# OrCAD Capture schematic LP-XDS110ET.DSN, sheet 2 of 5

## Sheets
2 2_XDS110: size A3
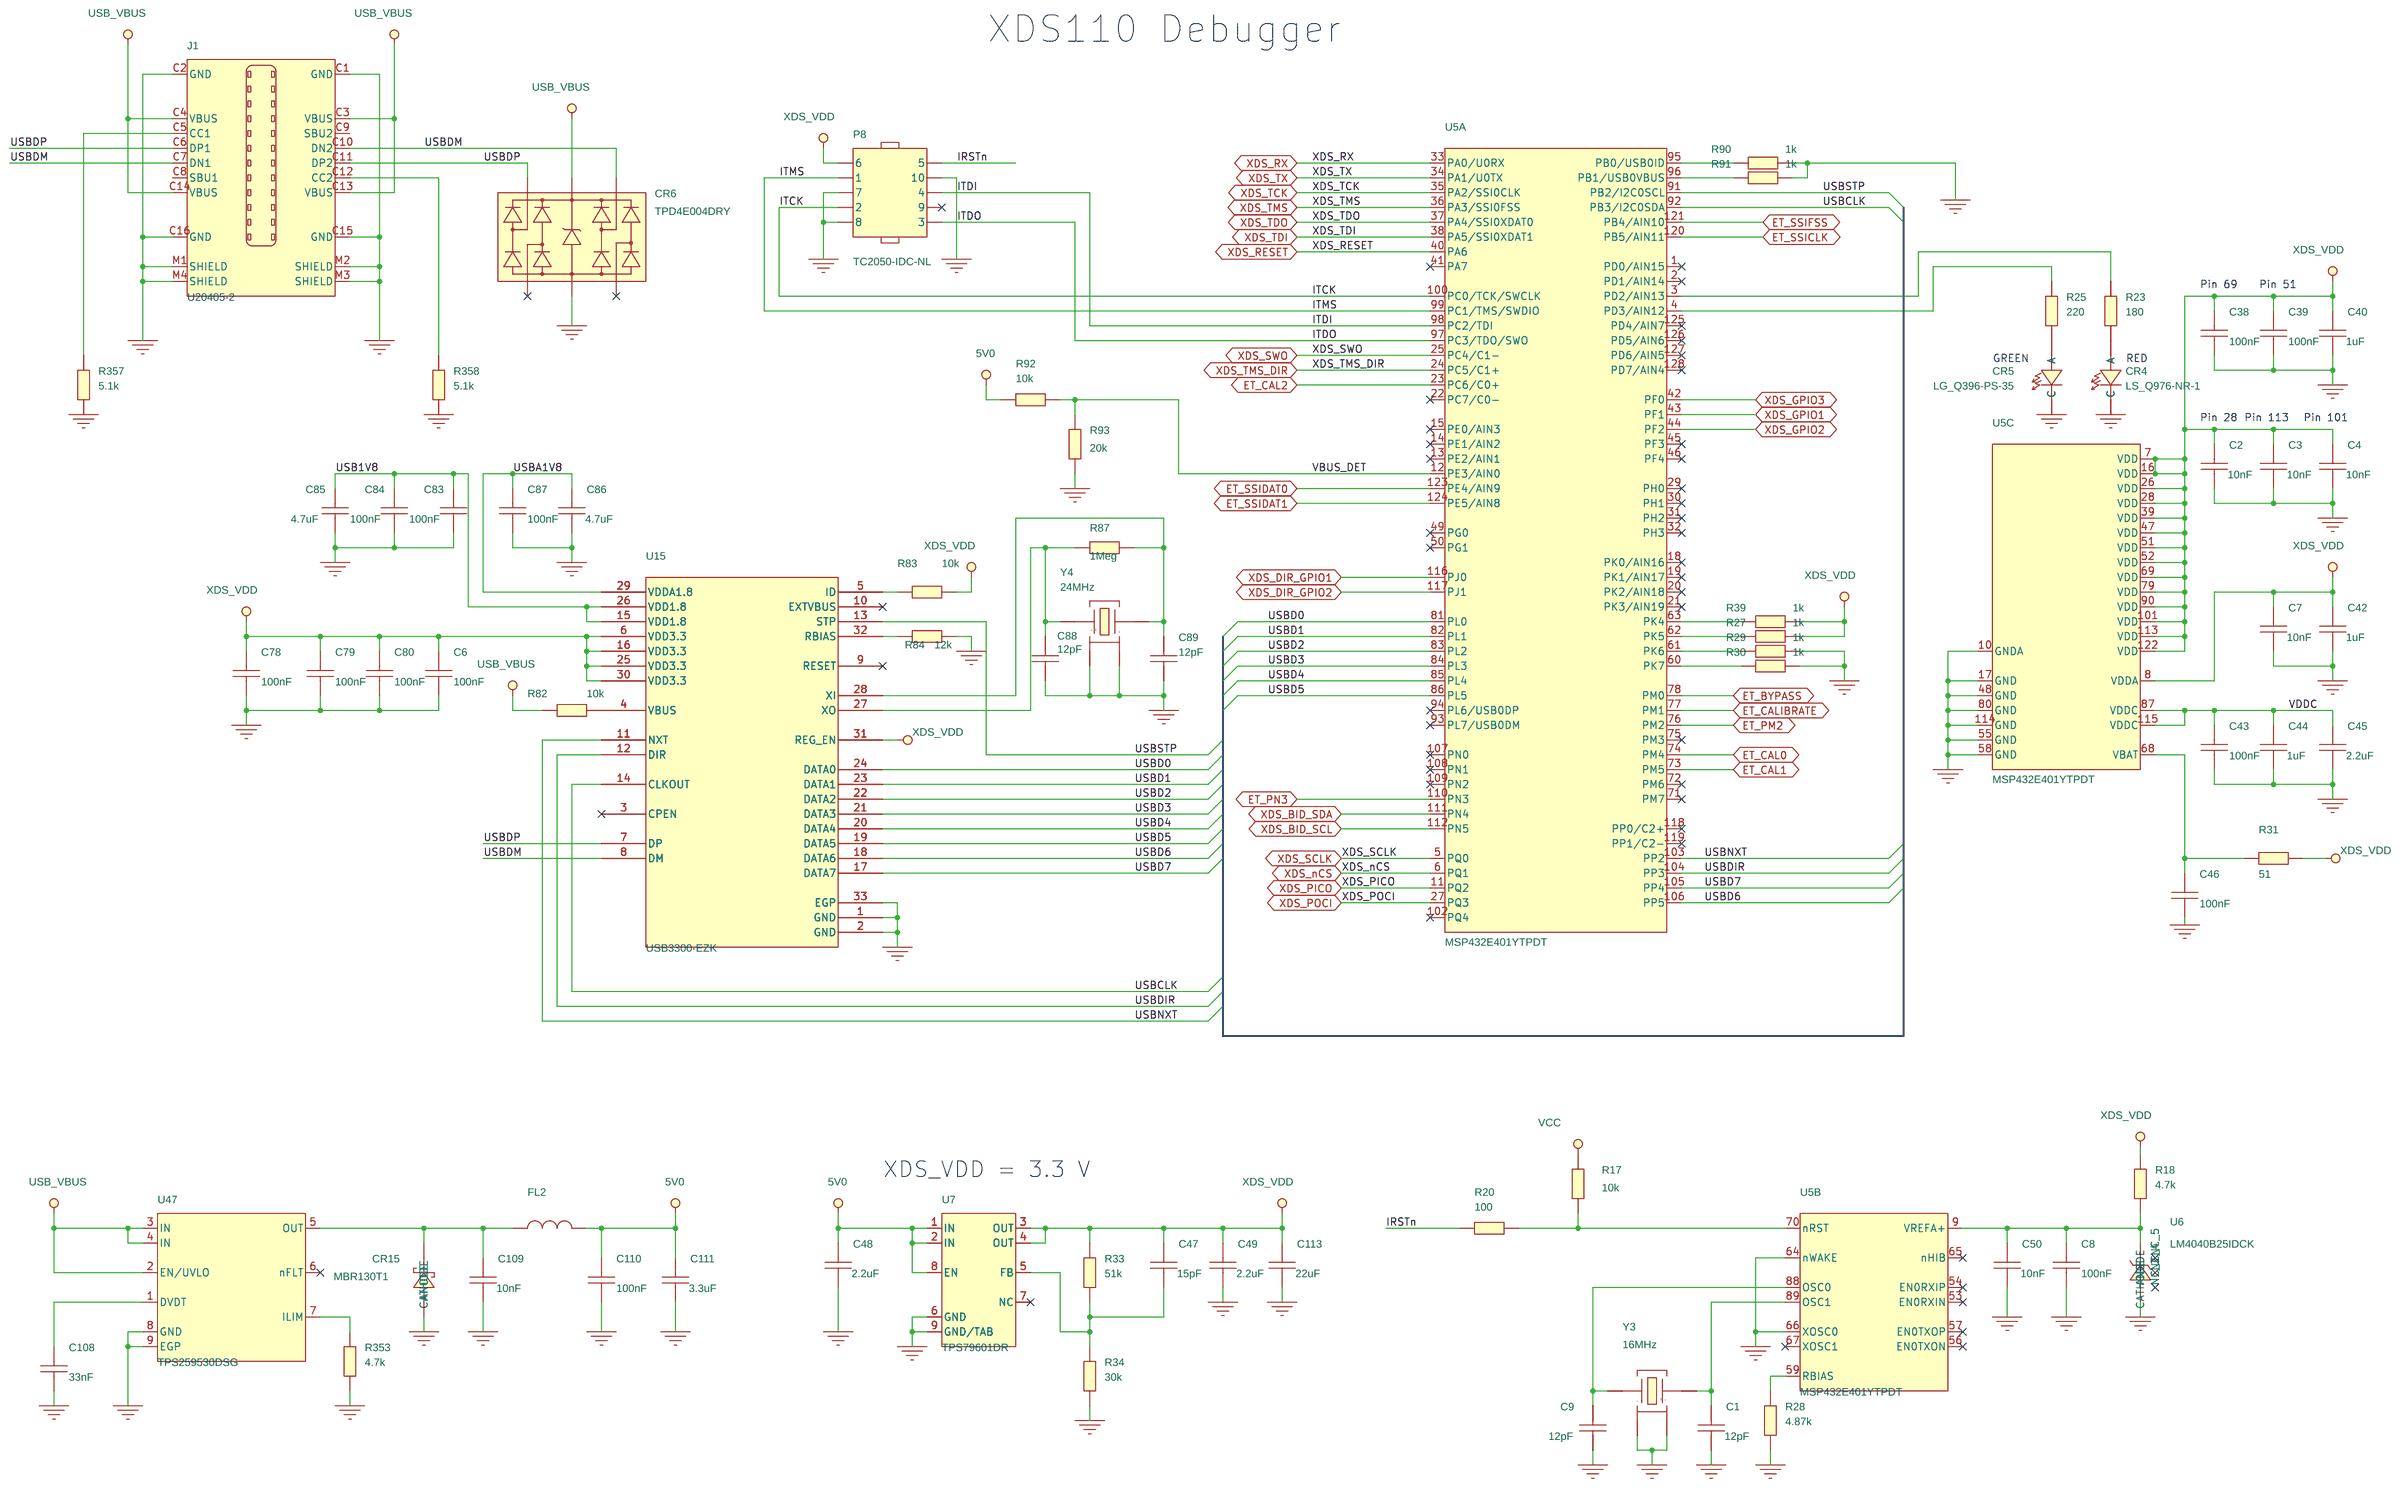
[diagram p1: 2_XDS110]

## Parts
C1  12pF  [CAPC1005X60B2N]
C2  10nF  [CAPC1005X60B2N]
C3  10nF  [CAPC1005X60B2N]
C4  10nF  [CAPC1005X60B2N]
C6  100nF  [CAPC0603X35B2N]
C7  10nF  [CAPC1005X60B2N]
C8  100nF  [CAPC0603X35B2N]
C9  12pF  [CAPC1005X60B2N]
C38  100nF  [CAPC0603X35B2N]
C39  100nF  [CAPC0603X35B2N]
C40  1uF  [CAPC1005X60B2N]
C42  1uF  [CAPC1005X60B2N]
C43  100nF  [CAPC0603X35B2N]
C44  1uF  [CAPC1005X60B2N]
C45  2.2uF  [CAPC1005X60A2N]
C46  100nF  [CAPC0603X35B2N]
C47  15pF  [CAPC1005X60B2N]
C48  2.2uF  [CAPC1005X60A2N]
C49  2.2uF  [CAPC1005X60A2N]
C50  10nF  [CAPC1005X60B2N]
C78  100nF  [CAPC0603X35B2N]
C79  100nF  [CAPC0603X35B2N]
C80  100nF  [CAPC0603X35B2N]
C83  100nF  [CAPC0603X35B2N]
C84  100nF  [CAPC0603X35B2N]
C85  4.7uF  [CAPC1005X60B2N]
C86  4.7uF  [CAPC1005X60B2N]
C87  100nF  [CAPC0603X35B2N]
C88  12pF  [CAPC1005X60B2N]
C89  12pF  [CAPC1005X60B2N]
C108  33nF  [CAPC1005X60A2N]
C109  10nF  [CAPC1005X60B2N]
C110  100nF  [CAPC0603X35B2N]
C111  3.3uF  [CAPC1608X100A2N]
C113  22uF  [CAPC1608X100A2N]
CR4  LS_Q976-NR-1  [LEDC1608X80B2N]
CR5  LG_Q396-PS-35  [LEDC1608X40N]
CR6  TPD4E004DRY  [SON50P100X145X60-6N]
CR15  MBR130T1  [SOD3716X135N]
FL2  BLM18HE152SN1  [FIL_BLM18HE152SN1DN]
J1  U20405-2  [MUP_U204052_A2N]
P8  TC2050-IDC-NL  [TAGCONNECT_TC2050IDCNL_A2N]
R17  10k  [RESC0603X35B2N]
R18  4.7k  [RESC1005X40B2N]
R20  100  [RESC1005X40B2N]
R23  180  [RESC1005X40B2N]
R25  220  [RESC1005X40B2N]
R27  1k  [RESC0603X35B2N]
R28  4.87k  [RESC1005X40B2N]
R29  1k  [RESC0603X35B2N]
R30  1k  [RESC0603X35B2N]
R31  51  [RESC0603X35B2N]
R33  51k  [RESC1005X40B2N]
R34  30k  [RESC1005X40B2N]
R39  1k  [RESC0603X35B2N]
R82  10k  [RESC0603X35B2N]
R83  10k  [RESC0603X35B2N]
R84  12k  [RESC0603X35B2N]
R87  1Meg  [RESC1005X40B2N]
R90  1k  [RESC0603X35B2N]
R91  1k  [RESC0603X35B2N]
R92  10k  [RESC0603X35B2N]
R93  20k  [RESC0603X35B2N]
R353  4.7k  [RESC1005X40B2N]
R357  5.1k  [RESC0603X35B2N]
R358  5.1k  [RESC0603X35B2N]
U5  MSP432E401YTPDT  [QFP40P1600X1600X120-128A2N]  (sections A,B,C)
U6  LM4040B25IDCK  [SOT65P210X110-5N]
U7  TPS79601DR  [SON65P300X300X100-9AN]
U15  USB3300-EZK  [QFNWB50P500X500X100-33N]
U47  TPS259530DSG  [SON50P200X200X80-9A2N]
Y3  16MHz  [OSCCC250X320X100-4BN]
Y4  24MHz  [OSCCC250X320X70-4AN]

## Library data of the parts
C1 C9 C88 C89 = CAPACITOR: CAPACITOR, CERAMIC C0G/NP0, 12pF, 50V, -5%/+5%, -55DEGC/+125DEGC, 0402, SMD; Additional Datasheet URL: http://psearch.en.murata.com/capacitor/product/GRM1555C1H120JA01%23.html; AutoDoc File: https://notefied-dynamic-precision.com/DB/Apps/Desktop/Item/Object.aspx?id=113345; BU Name: TEXAS INSTRUMENTS NORWAY; Budget Currency: EUR; Budget Price: 0.007; Budgetary Price: 0.007 EUR; Country of Origin: Philippines; Datasheet URL: http://psearch.murata.com/capacitor/product/GRM1555C1H120JA01%23.pdf; Datasheet URL 1: http://psearch.murata.com/capacitor/product/GRM1555C1H120JA01%23.pdf; Datasheet URL 2: http://search.murata.co.jp/Ceramy/image/img/w_hinm/L0005E.pdf; Definied Quality: INDUSTRIAL; Dielectric Type: C0G/NP0; Esd Level: N/A; Exclusive for Customers: TEXAS INSTRUMENTS NORWAY; Lead Time: 12; LifeCycle Status: ACTIVE; MPN: CAPACITOR_0402_12pF_C0G/NP0_M_+/-5%_50V; MPN Status: ACTIVE; MSL: N/A; MTBF: N/A; MTBF Standard: N/A; Manufacturer: MANUFACTURER SELECTION; Mass: 0.0016g; Max Oper Temp: +125DEGC; Max Tol: +5%; Maximum Operating Temperature: +125DEGC; Maximum Tolerance: +5%; Min Oper Temp: -55DEGC; Min Tol: -5%; Minimum Operating Temperature: -55DEGC; Minimum Tolerance: -5%; Mounting Type: SMD; NOTE Status: PREFERRED; NOTEfied URL: https://notefied-dynamic-precision.com/NOTEfiedWebInterface/part/show?partNumber=02-07617; Notes: Standard item: Duplicate Reason: custom footprint for TEXAS INSTRUMENTS NORWAY.; Old Footprint: CAPC1005X60N; PCB Package: 0402; Packing Size: 10000; Packing Type: Tape & Reel; Part Number: 02-07617; Part Type: Capacitor|CERAMIC|0402|STANDARD; REACH/SVHC Compliance: Compliant; REACH/SVHC Details: SVHC List Version Jul 7, 2017; REACH/SVHC Source: REACH Declaration; REACH/SVHC Status: Unaffected; REACH/SVHC_COMPLIANCE: COMPLIANT; REACH/SVHC_DETAILS: SVHC LIST VERSION Dec 17, 2015; REACH/SVHC_SOURCE: REACH DECLARATION; REACH/SVHC_STATUS: UNAFFECTED; ROHS: Compliant; Rated Voltage: 50V; Revision: R009; RoHS Status: ROHS_COMPLIANT; Rtd Voltage: 50V; Status: Released; Texas Part Status: Under Review; Type: Capacitor; Vendor: MURATA; Vendor Part Number: GRM1555C1H120JA01D; Vendor Part Status: Active; WEIGHT: 0.0016g
C2-C4 C7 C50 = CAPACITOR: CAPACITOR, CERAMIC X7R, 10nF, 25V, -10%/+10%, -55DEGC/+125DEGC, 0402, SMD; Additional Datasheet URL: http://psearch.en.murata.com/capacitor/product/GRM155R71E103KA01%23.html; AutoDoc File: https://notefied-dynamic-precision.com/DB/Apps/Desktop/Item/Object.aspx?id=114570; BU Name: TEXAS INSTRUMENTS NORWAY; Budget Currency: EUR; Budget Price: 0.003; Budgetary Price: 0.003 EUR; Client Status: UNDER_REVIEW; Country of Origin: China; Datasheet URL: http://psearch.murata.com/capacitor/product/GRM155R71E103KA01%23.pdf; Datasheet URL 1: http://psearch.murata.com/capacitor/product/GRM155R71E103KA01%23.pdf; Datasheet URL 2: http://search.murata.co.jp/Ceramy/image/img/w_hinm/L0005E.pdf; Definied Quality: INDUSTRIAL; Dielectric Type: X7R; Esd Level: N/A; Exclusive for Customers: TEXAS INSTRUMENTS NORWAY; Lead Time: 18; LifeCycle Status: ACTIVE; MPN: CAPACITOR_0402_10nF_X7R_M_+/-10%_25V; MPN Status: ACTIVE; MSL: N/A; MTBF: N/A; MTBF Standard: N/A; Manufacturer: MANUFACTURER SELECTION; Mass: 0.0016g; Max Oper Temp: +125DEGC; Max Tol: +10%; Maximum Operating Temperature: +125DEGC; Maximum Tolerance: +10%; Min Oper Temp: -55DEGC; Min Tol: -10%; Minimum Operating Temperature: -55DEGC; Minimum Tolerance: -10%; Mounting Type: SMD; NOTE Status: PREFERRED; NOTEfied URL: https://notefied-dynamic-precision.com/NOTEfiedWebInterface/part/show?partNumber=02-07775; Notes: Standard item: Duplicate Reason: custom footprint for TEXAS INSTRUMENTS NORWAY.; Old Footprint: CAPC1005X60N; PCB Package: 0402; Packing Size: 10000; Packing Type: Tape & Reel; Part Number: 02-07775; Part Type: Capacitor|CERAMIC|0402|STANDARD; REACH/SVHC Compliance: Compliant; REACH/SVHC Details: SVHC List Version Jul 7, 2017; REACH/SVHC Source: REACH Declaration; REACH/SVHC Status: Unaffected; REACH/SVHC_COMPLIANCE: COMPLIANT; REACH/SVHC_DETAILS: SVHC LIST VERSION Dec 17, 2015; REACH/SVHC_SOURCE: MATERIAL DECLARATION; REACH/SVHC_STATUS: UNAFFECTED; ROHS: Compliant; Rated Voltage: 25V; Revision: R013; RoHS Status: ROHS_COMPLIANT; Rtd Voltage: 25V; Status: Released; Texas Part Status: Under Review; Type: Capacitor; Vendor: MURATA; Vendor Part Number: GRM155R71E103KA01D; Vendor Part Status: Active; WEIGHT: 0.0016g
C6 C8 C38 C39 C43 C46 C78-C80 C110 = CAPACITOR: CAPACITOR, CERAMIC X5R, 100nF, 10V, -10%/+10%, -55DEGC/+85DEGC, 0201, SMD; ALT_SYMBOLS: CAPC0603X35B2L,CAPC0603X35B2M; Additional Datasheet URL: http://psearch.en.murata.com/capacitor/product/GRM033R61A104KE84%23.html; AutoDoc File: https://notefied-dynamic-precision.com/DB/Apps/Desktop/Item/Object.aspx?id=96679; BU Name: DYNAMIC PRECISION GDANSK; Budget Currency: EUR; Budget Price: 0.008; Budgetary Price: 0.008 EUR; Client Status: UNDER_REVIEW; Country of Origin: Missing Info; Datasheet URL: http://psearch.murata.com/capacitor/product/GRM033R61A104KE84%23.pdf; Datasheet URL 1: http://psearch.murata.com/capacitor/product/GRM033R61A104KE84%23.pdf; Datasheet URL 2: http://search.murata.co.jp/Ceramy/image/img/w_hinm/L0005E.pdf; Dielectric Type: X5R; Lead Time: 17; LifeCycle Status: ACTIVE; MPN: GRM155R70J104KA01D; MPN Status: ACTIVE; Manufacturer: MURATA; Mass: 0.00033g; Max Oper Temp: +85DEGC; Max Tol: +10%; Maximum Operating Temperature: +85DEGC; Maximum Tolerance: +10%; Min Oper Temp: -55DEGC; Min Tol: -10%; Minimum Operating Temperature: -55DEGC; Minimum Tolerance: -10%; Mounting Type: SMD; NOTE Status: PREFERRED; NOTEfied URL: https://notefied-dynamic-precision.com/NOTEfiedWebInterface/part/show?partNumber=02-06085; Old Footprint: CAPC1005X60N,0402; PCB Package: 0201; Packing Size: 15000; Packing Type: Tape & Reel; Part Number: 02-06085; Part Type: Capacitor|CERAMIC|0201|STANDARD; REACH/SVHC Compliance: Compliant; REACH/SVHC Details: SVHC List Version Jul 7, 2017; REACH/SVHC Source: REACH Declaration; REACH/SVHC Status: Unaffected; REACH/SVHC_COMPLIANCE: COMPLIANT; REACH/SVHC_DETAILS: SVHC LIST VERSION Jun 20, 2016; REACH/SVHC_SOURCE: REACH DECLARATION; REACH/SVHC_STATUS: UNAFFECTED; ROHS: Compliant; Rated Voltage: 10V; Revision: R011; RoHS Status: ROHS_COMPLIANT; Rtd Voltage: 10V; Status: Released; Texas Part Status: Under Review; Type: Capacitor; Vendor: MURATA; Vendor Part Number: GRM033R61A104KE84D; Vendor Part Status: Active; WEIGHT: 0.00033g
C40 C42 C44 = CAPACITOR: CAPACITOR, CERAMIC X5R, 1uF, 16V, -10%/+10%, -55DEGC/+85DEGC, 0402, SMD; Additional Datasheet URL: http://psearch.en.murata.com/capacitor/product/GRM155R61C105KA12%23.html; AutoDoc File: https://notefied-dynamic-precision.com/DB/Apps/Desktop/Item/Object.aspx?id=115295; BU Name: TEXAS INSTRUMENTS NORWAY; Client Status: UNDER_REVIEW; Datasheet URL: http://psearch.murata.com/capacitor/product/GRM155R61C105KA12%23.pdf; Datasheet URL 1: http://psearch.en.murata.com/capacitor/product/GRM155R61C105KA12%23.pdf; Datasheet URL 2: http://search.murata.co.jp/Ceramy/image/img/w_hinm/L0005E.pdf; Definied Quality: INDUSTRIAL; Dielectric Type: X5R; Esd Level: N/A; MPN: GRM155R61A105KE15D; MPN Status: ACTIVE; MSL: 1; MTBF: N/A; MTBF Standard: N/A; Manufacturer: MURATA; Mass: 0.0016g; Max Oper Temp: +85DEGC; Max Tol: +10%; Maximum Operating Temperature: +85DEGC; Maximum Tolerance: +10%; Min Oper Temp: -55DEGC; Min Tol: -10%; Minimum Operating Temperature: -55DEGC; Minimum Tolerance: -10%; Mounting Type: SMD; NOTE Status: PREFERRED; NOTEfied URL: https://notefied-dynamic-precision.com/NOTEfiedWebInterface/part/show?partNumber=02-07863; Old Footprint: CAPC1005X60N,0402; PCB Package: 0402; Packing Size: 10000; Packing Type: Tape & Reel; Part Number: 02-07863; Part Type: Capacitor|CERAMIC|0402|STANDARD; REACH/SVHC Compliance: Compliant; REACH/SVHC Details: SVHC List Version Jul 7, 2017; REACH/SVHC Source: REACH Declaration; REACH/SVHC Status: Unaffected; REACH/SVHC_COMPLIANCE: COMPLIANT; REACH/SVHC_DETAILS: SVHC LIST VERSION Jun 20, 2016; REACH/SVHC_SOURCE: REACH DECLARATION; REACH/SVHC_STATUS: UNAFFECTED; ROHS: Compliant; Rated Voltage: 16V; Revision: R008; RoHS Status: ROHS_COMPLIANT; Rtd Voltage: 16V; Status: Released; Texas Part Status: Under Review; Type: Capacitor; Vendor: MURATA; Vendor Part Number: GRM155R61C105KA12D; Vendor Part Status: Active; WEIGHT: 0.0016g
C45 C48 C49 = CAPACITOR: CAPACITOR, CERAMIC X5R, 2.2uF, 25V, -10%/+10%, -55DEGC/+85DEGC, 0402, SMD; ALT_SYMBOLS: CAPC1005X60A2L,CAPC1005X60A2M; Additional Datasheet URL: http://search.murata.co.jp/Ceramy/image/img/w_hinm/L0005E.pdf; AutoDoc File: https://notefied-dynamic-precision.com/DB/Apps/Desktop/Item/Object.aspx?id=96297; BU Name: DYNAMIC PRECISION GDANSK; Budget Currency: EUR; Budget Price: 0.063; Budgetary Price: 0.063 EUR; Client Status: UNDER_REVIEW; Country of Origin: Missing Info; Datasheet URL: http://psearch.murata.com/capacitor/product/GRM155R61E225KE11%23.pdf; Datasheet URL 1: http://psearch.murata.com/capacitor/product/GRM155R61E225KE11%23.pdf; Datasheet URL 2: http://search.murata.co.jp/Ceramy/image/img/w_hinm/L0005E.pdf; Definied Quality: INDUSTRIAL; Dielectric Type: X5R; Esd Level: N/A; Lead Time: 19; LifeCycle Status: NRND; MPN: GRM155R60J225KE95D; MPN Status: NRND; MSL: 1; MTBF: N/A; MTBF Standard: N/A; Manufacturer: MURATA; Mass: 0.0031g; Max Oper Temp: +85DEGC; Max Tol: +10%; Maximum Operating Temperature: +85DEGC; Maximum Tolerance: +10%; Min Oper Temp: -55DEGC; Min Tol: -10%; Minimum Operating Temperature: -55DEGC; Minimum Tolerance: -10%; Mounting Type: SMD; NOTE Status: PREFERRED; NOTEfied URL: https://notefied-dynamic-precision.com/NOTEfiedWebInterface/part/show?partNumber=02-06058; Old Footprint: CAPC1005X60N; PCB Package: 0402; Packing Size: 10000; Packing Type: Tape & Reel; Part Number: 02-06058; Part Type: Capacitor|CERAMIC|0402|STANDARD; REACH/SVHC Compliance: Compliant; REACH/SVHC Details: SVHC List Version Jul 7, 2017; REACH/SVHC Source: REACH Declaration; REACH/SVHC Status: Unaffected; REACH/SVHC_COMPLIANCE: COMPLIANT; REACH/SVHC_DETAILS: SVHC List Version Jun 20, 2016; REACH/SVHC_SOURCE: REACH DECLARATION; REACH/SVHC_STATUS: UNAFFECTED; ROHS: Compliant; Rated Voltage: 25V; Revision: R007; RoHS Status: ROHS_COMPLIANT; Rtd Voltage: 25V; Status: Released; Texas Part Status: Under Review; Type: Capacitor; Vendor: MURATA; Vendor Part Number: GRM155R61E225KE11D; Vendor Part Status: Active; WEIGHT: 0.0031g
C47 = CAPACITOR: CAPACITOR, CERAMIC C0G/NP0, 15pF, 50V, -5%/+5%, -55DEGC/+125DEGC, 0402, SMD; Additional Datasheet URL: http://psearch.en.murata.com/capacitor/product/GRM1555C1H150JA01%23.html; AutoDoc File: https://notefied-dynamic-precision.com/DB/Apps/Desktop/Item/Object.aspx?id=114571; BU Name: TEXAS INSTRUMENTS NORWAY; Budget Currency: EUR; Budget Price: 0.006; Budgetary Price: 0.006 EUR; Client Status: UNDER_REVIEW; Country of Origin: Philippines; Datasheet URL: http://psearch.murata.com/capacitor/product/GRM1555C1H150JA01%23.pdf; Datasheet URL 1: http://psearch.murata.com/capacitor/product/GRM1555C1H150JA01%23.pdf; Datasheet URL 2: http://search.murata.co.jp/Ceramy/image/img/w_hinm/L0005E.pdf; Definied Quality: INDUSTRIAL; Dielectric Type: C0G/NP0; Esd Level: N/A; Exclusive for Customers: TEXAS INSTRUMENTS NORWAY; Lead Time: 12; LifeCycle Status: ACTIVE; MPN: CAPACITOR_0402_15pF_C0G/NP0_M_+/-5%_50V; MPN Status: ACTIVE; MSL: N/A; MTBF: N/A; MTBF Standard: N/A; Manufacturer: MANUFACTURER SELECTION; Mass: 0.0016g; Max Oper Temp: +125DEGC; Max Tol: +5%; Maximum Operating Temperature: +125DEGC; Maximum Tolerance: +5%; Min Oper Temp: -55DEGC; Min Tol: -5%; Minimum Operating Temperature: -55DEGC; Minimum Tolerance: -5%; Mounting Type: SMD; NOTE Status: PREFERRED; NOTEfied URL: https://notefied-dynamic-precision.com/NOTEfiedWebInterface/part/show?partNumber=02-07776; Notes: Standard item: Duplicate Reason: custom footprint for TEXAS INSTRUMENTS NORWAY.; Old Footprint: CAPC1005X60N; PCB Package: 0402; Packing Size: 10000; Packing Type: Tape & Reel; Part Number: 02-07776; Part Type: Capacitor|CERAMIC|0402|STANDARD; REACH/SVHC Compliance: Compliant; REACH/SVHC Details: SVHC List Version Jul 7, 2017; REACH/SVHC Source: REACH Declaration; REACH/SVHC Status: Unaffected; REACH/SVHC_COMPLIANCE: COMPLIANT; REACH/SVHC_DETAILS: SVHC LIST VERSION Dec 17, 2015; REACH/SVHC_SOURCE: REACH DECLARATION; REACH/SVHC_STATUS: UNAFFECTED; ROHS: Compliant; Rated Voltage: 50V; Revision: R009; RoHS Status: ROHS_COMPLIANT; Rtd Voltage: 50V; Status: Released; Texas Part Status: Under Review; Type: Capacitor; Vendor: MURATA; Vendor Part Number: GRM1555C1H150JA01D; Vendor Part Status: Active; WEIGHT: 0.0016g
C83 C84 C87 = CAPACITOR: CAPACITOR, CERAMIC X5R, 100nF, 10V, -10%/+10%, -55DEGC/+85DEGC, 0201, SMD; ALT_SYMBOLS: CAPC0603X35B2L,CAPC0603X35B2M; Additional Datasheet URL: http://psearch.en.murata.com/capacitor/product/GRM033R61A104KE84%23.html; AutoDoc File: https://notefied-dynamic-precision.com/DB/Apps/Desktop/Item/Object.aspx?id=96679; BU Name: DYNAMIC PRECISION GDANSK; Budget Currency: EUR; Budget Price: 0.008; Budgetary Price: 0.008 EUR; Client Status: UNDER_REVIEW; Country of Origin: Missing Info; Datasheet URL: http://psearch.murata.com/capacitor/product/GRM033R61A104KE84%23.pdf; Datasheet URL 1: http://psearch.murata.com/capacitor/product/GRM033R61A104KE84%23.pdf; Datasheet URL 2: N/A; Dielectric Type: X5R; Lead Time: 17; LifeCycle Status: ACTIVE; MPN: GRM155R70J104KA01D; MPN Status: ACTIVE; Manufacturer: MURATA; Mass: 0.00033g; Max Oper Temp: +85DEGC; Max Tol: +10%; Maximum Operating Temperature: +85DEGC; Maximum Tolerance: +10%; Min Oper Temp: -55DEGC; Min Tol: -10%; Minimum Operating Temperature: -55DEGC; Minimum Tolerance: -10%; Mounting Type: SMD; NOTE Status: PREFERRED; NOTEfied URL: https://notefied-dynamic-precision.com/NOTEfiedWebInterface/part/show?partNumber=02-06085; Old Footprint: CAPC1005X60N,0402; PCB Package: 0201; Packing Size: 15000; Packing Type: Tape & Reel; Part Number: 02-06085; Part Type: Capacitor|CERAMIC|0201|STANDARD; REACH/SVHC Compliance: Compliant; REACH/SVHC Details: SVHC List Version Jul 7, 2017; REACH/SVHC Source: REACH Declaration; REACH/SVHC Status: Unaffected; REACH/SVHC_COMPLIANCE: COMPLIANT; REACH/SVHC_DETAILS: SVHC LIST VERSION Dec 17, 2015; REACH/SVHC_SOURCE: REACH DECLARATION; REACH/SVHC_STATUS: UNAFFECTED; ROHS: Compliant; Rated Voltage: 10V; Revision: R011; RoHS Status: ROHS_COMPLIANT; Rtd Voltage: 10V; Status: Released; Texas Part Status: Under Review; Type: Capacitor; Vendor: MURATA; Vendor Part Number: GRM033R61A104KE84D; Vendor Part Status: Active; WEIGHT: 0.00033g
C85 C86 = CAPACITOR: CAPACITOR, CERAMIC X5R, 4.7uF, 6.3V, -20%/+20%, -55DEGC/+85DEGC, 0402, SMD; Additional Datasheet URL: https://search.murata.co.jp/Ceramy/image/img/A01X/G101/ENG/GRM155R60J475ME87-01A.pdf; Budgetary Price: 0.0198 USD; Country of Origin: Philippines; Datasheet URL: https://www.murata.com/-/media/webrenewal/support/library/catalog/products/capacitor/mlcc/c02e.ashx?la=en-gb; Dielectric Type: X5R; Exclusive for Customers: TEXAS INSTRUMENTS NORWAY; Lead Time: 11; Mass: 0.0025g; Maximum Operating Temperature: +85DEGC; Maximum Tolerance: +20%; Minimum Operating Temperature: -55DEGC; Minimum Tolerance: -20%; Mounting Type: SMD; NOTEfied URL: https://notefied-dynamic-precision.com/NOTEfiedWebInterface/part/show?partNumber=02-07629; Notes: Standard item: Duplicate Reason: custom footprint for TEXAS INSTRUMENTS NORWAY.; PCB Package: 0402; Packing Size: 10000; Packing Type: Tape & Reel; Part Number: 02-07629; Part Type: Capacitor|CERAMIC|0402|STANDARD; REACH/SVHC Compliance: Compliant; REACH/SVHC Details: SVHC List Version Jul 7, 2017; REACH/SVHC Source: REACH Declaration; REACH/SVHC Status: Unaffected; ROHS: Compliant; Rated Voltage: 6.3V; Revision: R027; Status: Released; Texas Part Status: Under Review; Type: Capacitor; Vendor: MURATA; Vendor Part Number: GRM155R60J475ME87D; Vendor Part Status: Active
C108 = CAPACITOR: CAPACITOR, CERAMIC X7R, 33nF, 25V, -10%/+10%, -55DEGC/+125DEGC, 0402, SMD; ALT_SYMBOLS: CAPC1005X60A2L,CAPC1005X60A2M; Additional Datasheet URL: http://psearch.en.murata.com/capacitor/product/GRM155R71E333KA88%23.html; AutoDoc File: https://notefied-dynamic-precision.com/DB/Apps/Desktop/Item/Object.aspx?id=115293; BU Name: TEXAS INSTRUMENTS NORWAY; Budgetary Price: 0.013 EUR; Client Status: UNDER_REVIEW; Country of Origin: Philippines,China; Datasheet URL: https://search.murata.co.jp/Ceramy/image/img/A01X/G101/ENG/GRM155R71E333KA88-01A.pdf; Datasheet URL 1: http://psearch.en.murata.com/capacitor/product/GRM155R71E104KE14%23.pdf; Datasheet URL 2: http://search.murata.co.jp/Ceramy/image/img/w_hinm/L0005E.pdf; Dielectric Type: X7R; Lead Time: 12; LifeCycle Status: ACTIVE; MPN: GRM155R70J104KA01D; MPN Status: ACTIVE; Manufacturer: MURATA; Mass: 0.0016g; Max Oper Temp: +125DEGC; Max Tol: +10%; Maximum Operating Temperature: +125DEGC; Maximum Tolerance: +10%; Min Oper Temp: -55DEGC; Min Tol: -10%; Minimum Operating Temperature: -55DEGC; Minimum Tolerance: -10%; Mounting Type: SMD; NOTE Status: PREFERRED; NOTEfied URL: https://notefied-dynamic-precision.com/NOTEfiedWebInterface/part/show?partNumber=02-04479; Old Footprint: CAPC1005X60N,0402; PCB Package: 0402; Packing Size: 10000; Packing Type: Tape & Reel; Part Number: 02-04479; Part Type: Capacitor|CERAMIC|0402|STANDARD; REACH/SVHC_COMPLIANCE: COMPLIANT; REACH/SVHC_DETAILS: SVHC LIST VERSION Jun 20, 2016; REACH/SVHC_SOURCE: REACH DECLARATION; REACH/SVHC_STATUS: UNAFFECTED; ROHS: Compliant; Rated Voltage: 25V; Revision: R017; RoHS Status: ROHS_COMPLIANT; Rtd Voltage: 25V; Status: Released; Type: Capacitor; Vendor: MURATA; Vendor Part Number: GRM155R71E333KA88D; Vendor Part Status: Active; WEIGHT: 0.0016g
C109 = CAPACITOR: CAPACITOR, CERAMIC X7R, 10nF, 25V, -10%/+10%, -55DEGC/+125DEGC, 0402, SMD; Additional Datasheet URL: http://psearch.en.murata.com/capacitor/product/GRM155R71E103KA01%23.html; Budgetary Price: 0.003 EUR; Country of Origin: China; Datasheet URL: https://search.murata.co.jp/Ceramy/image/img/A01X/G101/ENG/GRM155R71E103KA01-01A.pdf; Dielectric Type: X7R; Exclusive for Customers: TEXAS INSTRUMENTS NORWAY; Lead Time: 18; Mass: 0.0016g; Maximum Operating Temperature: +125DEGC; Maximum Tolerance: +10%; Minimum Operating Temperature: -55DEGC; Minimum Tolerance: -10%; Mounting Type: SMD; NOTEfied URL: https://notefied-dynamic-precision.com/NOTEfiedWebInterface/part/show?partNumber=02-07775; Notes: Standard item: Duplicate Reason: custom footprint for TEXAS INSTRUMENTS NORWAY.; PCB Package: 0402; Packing Size: 10000; Packing Type: Tape & Reel; Part Number: 02-07775; Part Type: Capacitor|CERAMIC|0402|STANDARD; REACH/SVHC Compliance: Compliant; REACH/SVHC Details: SVHC List Version Jul 7, 2017; REACH/SVHC Source: REACH Declaration; REACH/SVHC Status: Unaffected; ROHS: Compliant; Rated Voltage: 25V; Revision: R015; Status: Released; Texas Part Status: Under Review; Type: Capacitor; Vendor: MURATA; Vendor Part Number: GRM155R71E103KA01D; Vendor Part Status: Active
C111 = CAPACITOR: CAPACITOR, CERAMIC X7S, 3.3uF, 6.3V, -10%/+10%, -55DEGC/+125DEGC, 0603, SMD; ALT_SYMBOLS: CAPC1608X100A2L,CAPC1608X100A2M; Additional Datasheet URL: https://search.murata.co.jp/Ceramy/image/img/A01X/G101/ENG/GCJ188C70J335KE02-01.pdf; Budgetary Price: 0.07426 USD; Datasheet URL: https://www.murata.com/-/media/webrenewal/support/library/catalog/products/capacitor/mlcc/c03e.ashx?la=en-gb&cvid=20200707014404000000; Dielectric Type: X7S; Lead Time: 19; Mass: 0.0063g; Maximum Operating Temperature: +125DEGC; Maximum Tolerance: +10%; Minimum Operating Temperature: -55DEGC; Minimum Tolerance: -10%; Mounting Type: SMD; NOTEfied URL: https://notefied-dynamic-precision.com/NOTEfiedWebInterface/part/show?partNumber=02-10054; PCB Package: 0603; Packing Size: 4000; Packing Type: Tape & Reel; Part Number: 02-10054; Part Type: Capacitor|CERAMIC|0603|STANDARD; REACH/SVHC Compliance: Compliant; REACH/SVHC Details: SVHC List Version Jun 25, 2020; REACH/SVHC Source: REACH Declaration; REACH/SVHC Status: Unaffected; ROHS: Compliant; Rated Voltage: 6.3V; Revision: R002; Status: Released; Texas Part Status: Under Review; Type: Capacitor; Vendor: MURATA; Vendor Part Number: GCJ188C70J335KE02D; Vendor Part Status: Active
C113 = CAPACITOR: CAPACITOR, CERAMIC, X5R, 22uF, 6.3V, -20%/+20%, -55DEGC/+85DEGC, 0603, SMD; ALT_SYMBOLS: CAPC1608X100A2L,CAPC1608X100A2M; Additional Datasheet URL: http://psearch.en.murata.com/capacitor/product/GRM188R60J226MEA0%23.html; AutoDoc File: https://notefied-dynamic-precision.com/DB/Apps/Desktop/Item/Object.aspx?id=104385; BU Name: DYNAMIC PRECISION GDANSK; Budget Currency: EUR; Budget Price: 0.062; Budgetary Price: 0.062 EUR; Client Status: UNDER_REVIEW; Country of Origin: Japan; Datasheet URL: http://psearch.murata.com/capacitor/product/GRM188R60J226MEA0%23.pdf; Datasheet URL 1: http://psearch.murata.com/capacitor/product/GRM188R60J226MEA0%23.pdf; Datasheet URL 2: http://search.murata.co.jp/Ceramy/image/img/w_hinm/L0005E.pdf; Dielectric Type: X5R; Lead Time: 26; Mass: 0.0091g; Max Oper Temp: +85DEGC; Max Tol: +20%; Maximum Operating Temperature: +85DEGC; Maximum Tolerance: +20%; Min Oper Temp: -55DEGC; Min Tol: -20%; Minimum Operating Temperature: -55DEGC; Minimum Tolerance: -20%; Mounting Type: SMD; NOTEfied URL: https://notefied-dynamic-precision.com/NOTEfiedWebInterface/part/show?partNumber=02-07053; PCB Package: 0603; Packing Size: 4000; Packing Type: Tape & Reel; Part Number: 02-07053; Part Type: Capacitor|CERAMIC|0603|STANDARD; REACH/SVHC Compliance: Compliant; REACH/SVHC Details: SVHC List Version Jul 7, 2017; REACH/SVHC Source: REACH Declaration; REACH/SVHC Status: Unaffected; REACH/SVHC_COMPLIANCE: COMPLIANT; REACH/SVHC_DETAILS: SVHC LIST VERSION Dec 17, 2015; REACH/SVHC_SOURCE: REACH DECLARATION; REACH/SVHC_STATUS: UNAFFECTED; ROHS: Compliant; Rated Voltage: 6.3V; Revision: R008; RoHS Status: ROHS_COMPLIANT; Rtd Voltage: 6.3V; Status: Released; Texas Part Status: Under Review; Type: Capacitor; Vendor: MURATA; Vendor Part Number: GRM188R60J226MEA0D; Vendor Part Status: Active; Weight: 0.0091g
CR4 = LED: OPTO, LED, RED, 633nm, 2V, 0.02A, 0603, SMD; ALT_SYMBOLS: LEDC1608X80B2L,LEDC1608X80B2M; Additional Datasheet URL: https://www.osram.com/ecat/CHIPLED%C2%AE%200603%20LS%20Q976/com/en/class_pim_web_catalog_103489/global/prd_pim_device_2190658/; Budgetary Price: 0.047 EUR; Country of Origin: Missing Info; Datasheet URL: https://dammedia.osram.info/media/resource/hires/osram-dam-6494322/LS%20Q976_EN.pdf; Lead Time: 6; Mass: 0.0014g; Maximum Operating Temperature: +85DEGC; Minimum Operating Temperature: -30DEGC; Mounting Type: SMD; NOTEfied URL: https://notefied-dynamic-precision.com/NOTEfiedWebInterface/part/show?partNumber=15-01289; PCB Package: 0603; Packing Size: 4000; Packing Type: Tape & Reel; Part Number: 15-01289; Part Type: Opto|LED|0603; ROHS: Compliant; Rated Current: 0.02A; Rated Voltage: 2V; Revision: R026; Status: Released; Type: Opto; Vendor: OSRAM; Vendor Part Number: LS Q976-NR-1; Vendor Part Status: Active
CR5 = LED: OPTO, LED, GREEN, 573nm, 2V, 0.02A, 0603, SMD; ALT_SYMBOLS: LEDC1608X40L,LEDC1608X40M; Additional Datasheet URL: https://www.osram.com/ecat/CHIPLED%C2%AE%200603%20LG%20Q396/com/en/class_pim_web_catalog_103489/global/prd_pim_device_2190654/; Budgetary Price: 0.068 EUR; Country of Origin: Missing Info; Datasheet URL: https://dammedia.osram.info/media/resource/hires/osram-dam-5178070/LG%20Q396_EN.pdf; Lead Time: 6; Mass: 0.0013g; Maximum Operating Temperature: +85DEGC; Minimum Operating Temperature: -30DEGC; Mounting Type: SMD; NOTEfied URL: https://notefied-dynamic-precision.com/NOTEfiedWebInterface/part/show?partNumber=15-01287; PCB Package: 0603; Packing Size: 4000; Packing Type: Tape & Reel; Part Number: 15-01287; Part Type: Opto|LED|0603; ROHS: Compliant; Rated Current: 0.02A; Rated Voltage: 2V; Revision: R026; Status: Released; Type: Opto; Vendor: OSRAM; Vendor Part Number: LG Q396-PS-35; Vendor Part Status: Active
CR6 = DIODE_TPD4E004_SON6: DIODE, PROTECTION, ESD ARRAY, 4 CHANNEL, 6V TO 8V, -40DEGC/+85DEGC, SON6, SMD; ALT_SYMBOLS: SON50P100X145X65-6L,SON50P100X145X65-6M; AutoDoc File: http://notefied-dynamic-precision.com/DB/Apps/Desktop/Item/Object.aspx?id=96191; Budget Currency: USD; Budget Price: 0.22; Datasheet URL 1: http://www.ti.com/lit/ml/mpds221e/mpds221e.pdf; Datasheet URL 2: http://www.ti.com/lit/ds/symlink/tpd4e004.pdf; Definied Quality: INDUSTRIAL; Esd Level: HBM 15kV; FPLIST: SON50P100X145X60-6N,SON50P100X145X65-6N,SON50P100X145X65-6L,SON50P100X145X65-6M; Last Time Buy: N/A; Lead Time: 10; MPN: TPD4E004DRYR; MPN Status: ACTIVE; MSL: 1; MTBF: 9.90*10^8; MTBF Standard: CL=60%,Ta=55degC,Tt=125degC,Ea=0.7eV; Manufacturer: TEXAS INSTRUMENTS; Max Oper Temp: +85DEGC; Min Oper Temp: -40DEGC; Mounting Type: SMD; NOTE Status: PREFERRED; Old Footprint: SON50P100X145X60-6N,SON50P100X145X65-6N; PCB Package: SON6; Packing Size: 5000; Packing Type: TAPE_&_REEL; Part Number: 14-06172; Part Type: DIODE\PROTECTION; Revision: R002; RoHS Status: ROHS_COMPLIANT; Rtd Voltage: 6V TO 8V; WEIGHT: 0.0028462g
CR15 = DIODE_SCHOTTKY: DIODE, SCHOTTKY, 1A, 30V, -65DEGC/+125DEGC, SOD-123, SMD; ALT_SYMBOLS: SOD3716X135L,SOD3716X135M,SOD3716X135BN; Additional Datasheet URL: http://www.onsemi.com/pub/Collateral/425-04.PDF; Budgetary Price: 0.0867 USD; CLASS: IC; Country of Origin: China; Datasheet URL: http://www.onsemi.com/pub/Collateral/MBR130T1-D.PDF; Lead Time: 22; Mass: 0.01167g; Maximum Operating Temperature: +125DEGC; Minimum Operating Temperature: -65DEGC; Mounting Type: SMD; NOTEfied URL: https://notefied-dynamic-precision.com/NOTEfiedWebInterface/part/show?partNumber=14-03076; PCB Package: SOD-123; Packing Size: 3000; Packing Type: Tape & Reel; Part Number: 14-03076; Part Type: Diode|SCHOTTKY; ROHS: Compliant; Rated Current: 1A; Rated Voltage: 30V; Revision: R010; Status: Released; Type: Diode; Vendor: ON SEMICONDUCTOR; Vendor Part Number: MBR130T1G; Vendor Part Status: Active
FL2 = FILTER_2PIN: FILTER, EMI, FERRITE BEAD, 1500@100MHz, -25%/+25%, -55DEGC/+125DEGC, 0603, SMD; ALT_SYMBOLS: FIL_BLM18HE152SN1DL,FIL_BLM18HE152SN1DM; Additional Datasheet URL: http://www.murata.com/en-global/products/productdetail.aspx?cate=luNoiseSupprFilteChipFerriBead&partno=BLM18HE152SN1%23; AutoDoc File: http://notefied-dynamic-precision.com/DB/Apps/Desktop/Item/Object.aspx?id=85575; Budget Currency: EUR; Budget Price: 0.085; Budgetary Price: 0.065 EUR; CLASS: IC; Country of Origin: Japan,Singapore,Thailand; Datasheet URL: http://www.murata.com/en-global/api/pdfdownloadapi?cate=luNoiseSupprFilteChipFerriBead&partno=BLM18HE152SN1%23; Datasheet URL 1: http://search.murata.co.jp/Ceramy/image/img/PDF/ENG/L0110S0101BLM18H.pdf; Datasheet URL 2: http://search.murata.co.jp/Ceramy/image/img/PDF/ENG/L0110S0101BLM18H.pdf; FPLIST: FIL_BLM18HE152SN1DN,FIL_BLM18HE152SN1DL,FIL_BLM18HE152SN1DM; Frequency: 100MHz; Impedance: 1500; Inductance: N/A; Lead Time: 9; MPN: BLM18HE152SN1D; MPN Status: ACTIVE; Manufacturer: MURATA; Mass: 0.006g; Max Oper Temp: +125DEGC; Max Tol: +25%; Maximum Operating Temperature: +125DEGC; Maximum Tolerance: +25%; Min Oper Temp: -55DEGC; Min Tol: -25%; Minimum Operating Temperature: -55DEGC; Minimum Tolerance: -25%; Mounting Type: SMD; NOTE Status: PREFERRED; NOTEfied URL: https://notefied-dynamic-precision.com/NOTEfiedWebInterface/part/show?partNumber=04-00470; PCB Package: 0603; Packing Size: 4000; Packing Type: Tape & Reel; Part Number: 04-00470; Part Type: Filter|EMI|FERRITE BEAD|0603; REACH/SVHC Compliance: Compliant; REACH/SVHC Details: SVHC List Version Jul 7, 2017; REACH/SVHC Source: REACH Declaration; REACH/SVHC Status: Unaffected; ROHS: Compliant; Rated Current: 0.5A; Rated Voltage: N/A; Revision: R009; RoHS Status: ROHS_COMPLIANT; Rtd Current: 0.5A; Status: Released; Texas Part Status: Under Review; Type: Filter; Vendor: MURATA; Vendor Part Number: BLM18HE152SN1D; Vendor Part Status: Active; WEIGHT: 0.006g
J1 = CONN_USB_TYPE-C_16PINS: CONNECTOR, USB, USB-C, 2 ROW(S), 16 PINS, PITCH 0.4mm, SMD; ALT_SYMBOLS: MUP_U204052_A2L,MUP_U204052_A2M; Additional Datasheet URL: N/A; Datasheet URL: http://www.mupconnector.com/mobile/product/show/id/524.html; Mass: N/A; Maximum Operating Temperature: +85DEGC; Minimum Operating Temperature: -25DEGC; Mounting Type: SMD; NOTEfied URL: https://notefied-dynamic-precision.com/NOTEfiedWebInterface/part/show?partNumber=06-10854; Number of Positions: 16; Number of Rows: 2; Packing Size: N/A; Packing Type: Missing Info; Part Number: 06-10854; Part Type: Connector|USB|USB-C; Pitch: 0.4mm; REACH/SVHC Compliance: Missing Info; REACH/SVHC Details: N/A; REACH/SVHC Source: N/A; REACH/SVHC Status: Missing Info; ROHS: Compliant; Rated Current: 5A/1.25A/0.25A; Revision: R001; Status: Released; Texas Part Status: Under Review; Type: Connector; Vendor: MUP; Vendor Part Status: Active
P8 = CONN_IDC_TC2050-IDC-NL: NON COMPONENT, CONNECTOR, CABLE, PLUG OF NAILS, 10 PINS, 2 ROWS, SMD; ALT_SYMBOLS: TAGCONNECT_TC2050IDCNL_A2L,TAGCONNECT_TC2050IDCNL_A2M; Additional Datasheet URL: http://www.tag-connect.com/TC2050-IDC-NL; AutoDoc File: https://notefied-dynamic-precision.com/DB/Apps/Desktop/Item/Object.aspx?id=96644; BU Name: DYNAMIC PRECISION GDANSK; Budgetary Price: 39 USD; CLASS: IO; Country of Origin: Missing Info; Datasheet URL: http://www.tag-connect.com/Materials/TC2050-IDC-NL%20Datasheet.pdf; Mass: N/A; Maximum Operating Temperature: N/A; Minimum Operating Temperature: N/A; Mounting Type: SMD; NOTEfied URL: https://notefied-dynamic-precision.com/NOTEfiedWebInterface/part/show?partNumber=19-00452; Number of Positions: 10; Number of Rows: 2; Old Footprint: TAGCONNECT_TC2050IDCNLN; Packing Size: 1; Packing Type: Bulk; Part Number: 19-00452; Pitch: 1.27mm; ROHS: Compliant; Revision: R007; Status: Released; Texas Part Status: Under Review; Type: Non Component; Vendor: TAG-CONNECT; Vendor Part Status: Active
R17 R82 R83 R92 = RESISTOR: RESISTOR, THICK FILM, 10k, -5%/+5%, 0.05W, 30V, -55DEGC/+155DEGC, 0201, SMD; ALT_SYMBOLS: RESC0603X35B2L,RESC0603X35B2M; Additional Datasheet URL: N/A; AutoDoc File: https://notefied-dynamic-precision.com/DB/Apps/Desktop/Item/Object.aspx?id=59003; BU Name: DYNAMIC PRECISION GDANSK; Budget Currency: USD; Budget Price: 0.0041; Budgetary Price: 0.0041 USD; Country of Origin: Taiwan; Datasheet URL: http://www.vishay.com/docs/20052/crcw0201e3.pdf; Datasheet URL 1: http://www.vishay.com/docs/20052/crcw0201e3.pdf; Datasheet URL 2: N/A; Definied Quality: INDUSTRIAL; Esd Level: N/A; Lead Time: 7; LifeCycle Status: ACTIVE; MPN: RESISTOR_0402_10k_+/-5%_50V_0.063W_M_+/-200ppm; MPN Status: ACTIVE; MSL: N/A; MTBF: N/A; MTBF Standard: N/A; Manufacturer: MANUFACTURER SELECTION; Mass: 0.00017g; Max Oper Temp: +155DEGC; Max TC: +200PPM/DEGC; Max Tol: +5%; Maximum Operating Temperature: +155DEGC; Maximum Temperature Coefficient: +200PPM/DEGC; Maximum Tolerance: +5%; Min Oper Temp: -55DEGC; Min TC: -200PPM/DEGC; Min Tol: -5%; Minimum Operating Temperature: -55DEGC; Minimum Temperature Coeficient: -200PPM/DEGC; Minimum Tolerance: -5%; Mounting Type: SMD; NOTE Status: PREFERRED; NOTEfied URL: https://notefied-dynamic-precision.com/NOTEfiedWebInterface/part/show?partNumber=01-04196; Old Footprint: RESC1005X40N; PCB Package: 0201; Packing Size: 10000; Packing Type: Tape & Reel; Part Number: 01-04196; Part Type: Resistor|0201|STANDARD; REACH/SVHC Compliance: Compliant; REACH/SVHC Details: SVHC List Version Dec 17, 2015; REACH/SVHC Source: Material Declaration; REACH/SVHC Status: Unaffected; REACH/SVHC_COMPLIANCE: COMPLIANT; REACH/SVHC_DETAILS: SVHC LIST VERSION Dec 17, 2015; REACH/SVHC_SOURCE: MATERIAL DECLARATION; REACH/SVHC_STATUS: UNAFFECTED; ROHS: Exempt; Rated Current: N/A; Rated Power: 0.05W; Rated Voltage: 30V; Resistor Type: THICK FILM; Revision: R003; RoHS Status: ROHS_COMPLIANT; Rtd Current: N/A; Rtd Power: 0.05W; Rtd Voltage: 30V; Status: Released; Type: Resistor; Vendor: VISHAY; Vendor Part Number: CRCW020110K0JNED; Vendor Part Status: Active; WEIGHT: 0.00017g
R18 = RESISTOR: RESISTOR, THICK FILM, 4.7k, -5%/+5%, 0.063W, 50V, -55DEGC/+155DEGC, 0402, SMD; Additional Datasheet URL: N/A; AutoDoc File: https://notefied-dynamic-precision.com/DB/Apps/Desktop/Item/Object.aspx?id=114562; BU Name: TEXAS INSTRUMENTS NORWAY; Budget Currency: EUR; Budget Price: 0.014; Budgetary Price: 0.014 EUR; Client Status: UNDER_REVIEW; Country of Origin: Israel; Datasheet URL: http://www.vishay.com/docs/20035/dcrcwe3.pdf; Datasheet URL 1: http://www.vishay.com/docs/20035/dcrcwe3.pdf; Datasheet URL 2: N/A; Definied Quality: INDUSTRIAL; Esd Level: N/A; Exclusive for Customers: TEXAS INSTRUMENTS NORWAY; Lead Time: 18; LifeCycle Status: ACTIVE; MPN: RESISTOR_0402_4.7k_+/-5%_50V_0.063W_M_+/-200ppm; MPN Status: ACTIVE; MSL: N/A; MTBF: N/A; MTBF Standard: N/A; Manufacturer: MANUFACTURER SELECTION; Mass: 0.00065g; Max Oper Temp: +155DEGC; Max TC: +200PPM/DEGC; Max Tol: +5%; Maximum Operating Temperature: +155DEGC; Maximum Temperature Coefficient: +200PPM/DEGC; Maximum Tolerance: +5%; Min Oper Temp: -55DEGC; Min TC: -200PPM/DEGC; Min Tol: -5%; Minimum Operating Temperature: -55DEGC; Minimum Temperature Coeficient: -200PPM/DEGC; Minimum Tolerance: -5%; Mounting Type: SMD; NOTE Status: PREFERRED; NOTEfied URL: https://notefied-dynamic-precision.com/NOTEfiedWebInterface/part/show?partNumber=01-22489; Notes: Standard item: Duplicate Reason: custom footprint for TEXAS INSTRUMENTS NORWAY.; Old Footprint: RESC1005X40N; PCB Package: 0402; Packing Size: 10000; Packing Type: Tape & Reel; Part Number: 01-22489; Part Type: Resistor|0402|STANDARD; REACH/SVHC Compliance: Compliant; REACH/SVHC Details: SVHC List Version Jun 20, 2016; REACH/SVHC Source: Material Declaration; REACH/SVHC Status: Unaffected; REACH/SVHC_COMPLIANCE: COMPLIANT; REACH/SVHC_DETAILS: SVHC LIST VERSION Jun 20, 2016; REACH/SVHC_SOURCE: MATERIAL DECLARATION; REACH/SVHC_STATUS: UNAFFECTED; ROHS: Exempt; Rated Current: N/A; Rated Power: 0.063W; Rated Voltage: 50V; Resistor Type: THICK FILM; Revision: R007; RoHS Status: ROHS_COMPLIANT; Rtd Current: N/A; Rtd Power: 0.063W; Rtd Voltage: 50V; Status: Released; Texas Part Status: Under Review; Type: Resistor; Vendor: VISHAY; Vendor Part Number: CRCW04024K70JNED; Vendor Part Status: Active; WEIGHT: 0.00065g
R20 = RESISTOR: RESISTOR, THICK FILM, 100, -5%/+5%, 0.063W, 50V, -55DEGC/+155DEGC, 0402, SMD; Additional Datasheet URL: N/A; AutoDoc File: https://notefied-dynamic-precision.com/DB/Apps/Desktop/Item/Object.aspx?id=114555; BU Name: TEXAS INSTRUMENTS NORWAY; Budget Currency: USD; Budget Price: 0.0014; Budgetary Price: 0.0014 USD; Client Status: UNDER_REVIEW; Country of Origin: United States; Datasheet URL: http://www.vishay.com/docs/20035/dcrcwe3.pdf; Datasheet URL 1: http://www.vishay.com/docs/20035/dcrcwe3.pdf; Datasheet URL 2: N/A; Definied Quality: INDUSTRIAL; Esd Level: N/A; Exclusive for Customers: TEXAS INSTRUMENTS NORWAY; Lead Time: 16; LifeCycle Status: ACTIVE; MPN: RESISTOR_0402_100_+/-1%_50V_0.063W_M_+/-100ppm; MPN Status: ACTIVE; MSL: N/A; MTBF: N/A; MTBF Standard: N/A; Manufacturer: MANUFACTURER SELECTION; Mass: 0.00065g; Max Oper Temp: +155DEGC; Max TC: +200PPM/DEGC; Max Tol: +5%; Maximum Operating Temperature: +155DEGC; Maximum Temperature Coefficient: +200PPM/DEGC; Maximum Tolerance: +5%; Min Oper Temp: -55DEGC; Min TC: -200PPM/DEGC; Min Tol: -5%; Minimum Operating Temperature: -55DEGC; Minimum Temperature Coeficient: -200PPM/DEGC; Minimum Tolerance: -5%; Mounting Type: SMD; NOTE Status: PREFERRED; NOTEfied URL: https://notefied-dynamic-precision.com/NOTEfiedWebInterface/part/show?partNumber=01-22482; Notes: Standard item: Duplicate Reason: custom footprint for TEXAS INSTRUMENTS NORWAY.; Old Footprint: RESC1005X40N; PCB Package: 0402; Packing Size: 10000; Packing Type: Tape & Reel; Part Number: 01-22482; Part Type: Resistor|0402|STANDARD; REACH/SVHC Compliance: Compliant; REACH/SVHC Details: SVHC List Version Jun 20, 2016; REACH/SVHC Source: Material Declaration; REACH/SVHC Status: Unaffected; REACH/SVHC_COMPLIANCE: COMPLIANT; REACH/SVHC_DETAILS: SVHC LIST VERSION Jun 20, 2016; REACH/SVHC_SOURCE: MATERIAL DECLARATION; REACH/SVHC_STATUS: UNAFFECTED; ROHS: Exempt; Rated Current: N/A; Rated Power: 0.063W; Rated Voltage: 50V; Resistor Type: THICK FILM; Revision: R007; RoHS Status: ROHS_COMPLIANT; Rtd Current: N/A; Rtd Power: 0.063W; Rtd Voltage: 50V; Status: Released; Texas Part Status: Under Review; Type: Resistor; Vendor: VISHAY; Vendor Part Number: CRCW0402100RJNED; Vendor Part Status: Active; WEIGHT: 0.00065g
R23 = RESISTOR: RESISTOR, THICK FILM, 180, -5%/+5%, 0.063W, 50V, -55DEGC/+155DEGC, 0402, SMD; Additional Datasheet URL: N/A; AutoDoc File: https://notefied-dynamic-precision.com/DB/Apps/Desktop/Item/Object.aspx?id=113318; BU Name: TEXAS INSTRUMENTS NORWAY; Budget Currency: EUR; Budget Price: 0.014; Budgetary Price: 0.014 EUR; Client Status: UNDER_REVIEW; Country of Origin: Missing Info; Datasheet URL: http://www.vishay.com/docs/20035/dcrcwe3.pdf; Datasheet URL 1: http://www.vishay.com/docs/20035/dcrcwe3.pdf; Datasheet URL 2: N/A; Definied Quality: INDUSTRIAL; Esd Level: N/A; Exclusive for Customers: TEXAS INSTRUMENTS NORWAY; Lead Time: 18; LifeCycle Status: ACTIVE; MPN: RESISTOR_0402_180_+/-5%_50V_0.063W_M_+/-200ppm; MPN Status: ACTIVE; MSL: N/A; MTBF: N/A; MTBF Standard: N/A; Manufacturer: MANUFACTURER SELECTION; Mass: 0.00065g; Max Oper Temp: +155DEGC; Max TC: +200PPM/DEGC; Max Tol: +5%; Maximum Operating Temperature: +155DEGC; Maximum Temperature Coefficient: +200PPM/DEGC; Maximum Tolerance: +5%; Min Oper Temp: -55DEGC; Min TC: -200PPM/DEGC; Min Tol: -5%; Minimum Operating Temperature: -55DEGC; Minimum Temperature Coeficient: -200PPM/DEGC; Minimum Tolerance: -5%; Mounting Type: SMD; NOTE Status: PREFERRED; NOTEfied URL: https://notefied-dynamic-precision.com/NOTEfiedWebInterface/part/show?partNumber=01-22345; Notes: Standard item: Duplicate Reason: custom footprint for TEXAS INSTRUMENTS NORWAY.; Old Footprint: RESC1005X40N; PCB Package: 0402; Packing Size: 10000; Packing Type: Tape & Reel; Part Number: 01-22345; Part Type: Resistor|0402|STANDARD; REACH/SVHC Compliance: Compliant; REACH/SVHC Details: SVHC List Version Jun 20, 2016; REACH/SVHC Source: Material Declaration; REACH/SVHC Status: Unaffected; REACH/SVHC_COMPLIANCE: COMPLIANT; REACH/SVHC_DETAILS: SVHC LIST VERSION Jun 20, 2016; REACH/SVHC_SOURCE: MATERIAL DECLARATION; REACH/SVHC_STATUS: UNAFFECTED; ROHS: Exempt; Rated Current: N/A; Rated Power: 0.063W; Rated Voltage: 50V; Resistor Type: THICK FILM; Revision: R007; RoHS Status: ROHS_COMPLIANT_WITH_EXEMPTION; Rtd Current: N/A; Rtd Power: 0.063W; Rtd Voltage: 50V; Status: Released; Texas Part Status: Under Review; Type: Resistor; Vendor: VISHAY; Vendor Part Number: CRCW0402180RJNED; Vendor Part Status: Active; WEIGHT: 0.00065g
R25 = RESISTOR: RESISTOR, THICK FILM, 220, -5%/+5%, 0.063W, 50V, -55DEGC/+155DEGC, 0402, SMD; Additional Datasheet URL: N/A; AutoDoc File: https://notefied-dynamic-precision.com/DB/Apps/Desktop/Item/Object.aspx?id=113319; BU Name: TEXAS INSTRUMENTS NORWAY; Budget Currency: EUR; Budget Price: 0.014; Budgetary Price: 0.014 EUR; Client Status: UNDER_REVIEW; Country of Origin: Israel; Datasheet URL: http://www.vishay.com/docs/20035/dcrcwe3.pdf; Datasheet URL 1: http://www.vishay.com/docs/20035/dcrcwe3.pdf; Datasheet URL 2: N/A; Definied Quality: INDUSTRIAL; Esd Level: N/A; Exclusive for Customers: TEXAS INSTRUMENTS NORWAY; Lead Time: 18; LifeCycle Status: ACTIVE; MPN: RESISTOR_0402_220_+/-5%_50V_0.063W_M_+/-200ppm; MPN Status: ACTIVE; MSL: N/A; MTBF: N/A; MTBF Standard: N/A; Manufacturer: MANUFACTURER SELECTION; Mass: 0.00065g; Max Oper Temp: +155DEGC; Max TC: +200PPM/DEGC; Max Tol: +5%; Maximum Operating Temperature: +155DEGC; Maximum Temperature Coefficient: +200PPM/DEGC; Maximum Tolerance: +5%; Min Oper Temp: -55DEGC; Min TC: -200PPM/DEGC; Min Tol: -5%; Minimum Operating Temperature: -55DEGC; Minimum Temperature Coeficient: -200PPM/DEGC; Minimum Tolerance: -5%; Mounting Type: SMD; NOTE Status: PREFERRED; NOTEfied URL: https://notefied-dynamic-precision.com/NOTEfiedWebInterface/part/show?partNumber=01-22346; Notes: Standard item: Duplicate Reason: custom footprint for TEXAS INSTRUMENTS NORWAY.; Old Footprint: RESC1005X40N; PCB Package: 0402; Packing Size: 10000; Packing Type: Tape & Reel; Part Number: 01-22346; Part Type: Resistor|0402|STANDARD; REACH/SVHC Compliance: Compliant; REACH/SVHC Details: SVHC List Version Jun 20, 2016; REACH/SVHC Source: Material Declaration; REACH/SVHC Status: Unaffected; REACH/SVHC_COMPLIANCE: COMPLIANT; REACH/SVHC_DETAILS: SVHC LIST VERSION Jun 20, 2016; REACH/SVHC_SOURCE: MATERIAL DECLARATION; REACH/SVHC_STATUS: UNAFFECTED; ROHS: Exempt; Rated Current: N/A; Rated Power: 0.063W; Rated Voltage: 50V; Resistor Type: THICK FILM; Revision: R007; RoHS Status: ROHS_COMPLIANT_WITH_EXEMPTION; Rtd Current: N/A; Rtd Power: 0.063W; Rtd Voltage: 50V; Status: Released; Texas Part Status: Under Review; Type: Resistor; Vendor: VISHAY; Vendor Part Number: CRCW0402220RJNED; Vendor Part Status: Active; WEIGHT: 0.00065g
R27 R29 R30 R39 R90 R91 = RESISTOR: RESISTOR, THICK FILM, 1k, -5%/+5%, 0.05W, 30V, -55DEGC/+155DEGC, 0201, SMD; ALT_SYMBOLS: RESC0603X35B2L,RESC0603X35B2M; Additional Datasheet URL: N/A; AutoDoc File: https://notefied-dynamic-precision.com/DB/Apps/Desktop/Item/Object.aspx?id=58979; BU Name: DYNAMIC PRECISION GDANSK; Budget Currency: USD; Budget Price: 0.0041; Budgetary Price: 0.0041 USD; Country of Origin: Taiwan; Datasheet URL: http://www.vishay.com/docs/20052/crcw0201e3.pdf; Datasheet URL 1: http://www.vishay.com/docs/20052/crcw0201e3.pdf; Datasheet URL 2: N/A; Definied Quality: INDUSTRIAL; Esd Level: N/A; Lead Time: 7; LifeCycle Status: ACTIVE; MPN: RESISTOR_0402_1k_+/-5%_50V_0.063W_M_+/-200ppm; MPN Status: ACTIVE; MSL: N/A; MTBF: N/A; MTBF Standard: N/A; Manufacturer: MANUFACTURER SELECTION; Mass: 0.00017g; Max Oper Temp: +155DEGC; Max TC: +200PPM/DEGC; Max Tol: +5%; Maximum Operating Temperature: +155DEGC; Maximum Temperature Coefficient: +200PPM/DEGC; Maximum Tolerance: +5%; Min Oper Temp: -55DEGC; Min TC: -200PPM/DEGC; Min Tol: -5%; Minimum Operating Temperature: -55DEGC; Minimum Temperature Coeficient: -200PPM/DEGC; Minimum Tolerance: -5%; Mounting Type: SMD; NOTE Status: PREFERRED; NOTEfied URL: https://notefied-dynamic-precision.com/NOTEfiedWebInterface/part/show?partNumber=01-04172; Old Footprint: RESC1005X40N; PCB Package: 0201; Packing Size: 10000; Packing Type: Tape & Reel; Part Number: 01-04172; Part Type: Resistor|0201|STANDARD; REACH/SVHC Compliance: Compliant; REACH/SVHC Details: SVHC List Version Jan 12, 2017; REACH/SVHC Source: REACH Declaration; REACH/SVHC Status: Unaffected; ROHS: Exempt; Rated Current: N/A; Rated Power: 0.05W; Rated Voltage: 30V; Resistor Type: THICK FILM; Revision: R007; RoHS Status: ROHS_COMPLIANT; Rtd Current: N/A; Rtd Power: 0.05W; Rtd Voltage: 30V; Status: Released; Texas Part Status: Under Review; Type: Resistor; Vendor: VISHAY; Vendor Part Number: CRCW02011K00JNED; Vendor Part Status: Active; WEIGHT: 0.00017g
R28 = RESISTOR: RESISTOR, THICK FILM, 4.87k, -1%/+1%, 0.063W, 50V, -55DEGC/+155DEGC, 0402, SMD; Additional Datasheet URL: N/A; AutoDoc File: https://notefied-dynamic-precision.com/DB/Apps/Desktop/Item/Object.aspx?id=114567; BU Name: TEXAS INSTRUMENTS NORWAY; Budget Currency: EUR; Budget Price: 0.012; Budgetary Price: 0.012 EUR; Client Status: UNDER_REVIEW; Country of Origin: Israel; Datasheet URL: http://www.vishay.com/docs/20035/dcrcwe3.pdf; Datasheet URL 1: http://www.vishay.com/docs/20035/dcrcwe3.pdf; Datasheet URL 2: N/A; Definied Quality: INDUSTRIAL; Esd Level: N/A; Exclusive for Customers: TEXAS INSTRUMENTS NORWAY; Lead Time: 14; LifeCycle Status: ACTIVE; MPN: RESISTOR_0402_4.87k_+/-1%_50V_0.063W_M_+/-100ppm; MPN Status: ACTIVE; MSL: N/A; MTBF: N/A; MTBF Standard: N/A; Manufacturer: MANUFACTURER SELECTION; Mass: 0.00065g; Max Oper Temp: +155DEGC; Max TC: +100PPM/DEGC; Max Tol: +1%; Maximum Operating Temperature: +155DEGC; Maximum Temperature Coefficient: +100PPM/DEGC; Maximum Tolerance: +1%; Min Oper Temp: -55DEGC; Min TC: -100PPM/DEGC; Min Tol: -1%; Minimum Operating Temperature: -55DEGC; Minimum Temperature Coeficient: -100PPM/DEGC; Minimum Tolerance: -1%; Mounting Type: SMD; NOTE Status: PREFERRED; NOTEfied URL: https://notefied-dynamic-precision.com/NOTEfiedWebInterface/part/show?partNumber=01-22494; Notes: Standard item: Duplicate Reason: custom footprint for TEXAS INSTRUMENTS NORWAY.; Old Footprint: RESC1005X40N; PCB Package: 0402; Packing Size: 10000; Packing Type: Tape & Reel; Part Number: 01-22494; Part Type: Resistor|0402|PRECISION; REACH/SVHC Compliance: Compliant; REACH/SVHC Details: SVHC List Version Jun 20, 2016; REACH/SVHC Source: Material Declaration; REACH/SVHC Status: Unaffected; REACH/SVHC_COMPLIANCE: COMPLIANT; REACH/SVHC_DETAILS: SVHC LIST VERSION Jun 20, 2016; REACH/SVHC_SOURCE: MATERIAL DECLARATION; REACH/SVHC_STATUS: UNAFFECTED; ROHS: Exempt; Rated Current: N/A; Rated Power: 0.063W; Rated Voltage: 50V; Resistor Type: THICK FILM; Revision: R011; RoHS Status: ROHS_COMPLIANT_WITH_EXEMPTION; Rtd Current: N/A; Rtd Power: 0.063W; Rtd Voltage: 50V; Status: Released; Texas Part Status: Under Review; Type: Resistor; Vendor: VISHAY; Vendor Part Number: CRCW04024K87FKED; Vendor Part Status: Active; WEIGHT: 0.00065g
R31 = RESISTOR: RESISTOR, THICK FILM, 51, -5%/+5%, 0.05W, 30V, -55DEGC/+155DEGC, 0201, SMD; ALT_SYMBOLS: RESC0603X35B2L,RESC0603X35B2M; Additional Datasheet URL: N/A; AutoDoc File: https://notefied-dynamic-precision.com/DB/Apps/Desktop/Item/Object.aspx?id=114554; BU Name: TEXAS INSTRUMENTS NORWAY; Budget Currency: EUR; Budget Price: 0.014; Budgetary Price: 0.0041 USD; Client Status: UNDER_REVIEW; Country of Origin: Taiwan; Datasheet URL: http://www.vishay.com/docs/20052/crcw0201e3.pdf; Datasheet URL 1: http://www.vishay.com/docs/20035/dcrcwe3.pdf; Datasheet URL 2: N/A; Definied Quality: INDUSTRIAL; Esd Level: N/A; Lead Time: 7; LifeCycle Status: ACTIVE; MPN: RESISTOR_0402_51_+/-5%_50V_0.063W_M_+/-200ppm; MPN Status: ACTIVE; MSL: N/A; MTBF: N/A; MTBF Standard: N/A; Manufacturer: MANUFACTURER SELECTION; Mass: 0.00017g; Max Oper Temp: +155DEGC; Max TC: +200PPM/DEGC; Max Tol: +5%; Maximum Operating Temperature: +155DEGC; Maximum Temperature Coefficient: +200PPM/DEGC; Maximum Tolerance: +5%; Min Oper Temp: -55DEGC; Min TC: -200PPM/DEGC; Min Tol: -5%; Minimum Operating Temperature: -55DEGC; Minimum Temperature Coeficient: -200PPM/DEGC; Minimum Tolerance: -5%; Mounting Type: SMD; NOTE Status: PREFERRED; NOTEfied URL: https://notefied-dynamic-precision.com/NOTEfiedWebInterface/part/show?partNumber=01-04141; Old Footprint: RESC1005X40N; PCB Package: 0201; Packing Size: 10000; Packing Type: Tape & Reel; Part Number: 01-04141; Part Type: Resistor|0201|STANDARD; REACH/SVHC_COMPLIANCE: COMPLIANT; REACH/SVHC_DETAILS: SVHC LIST VERSION Jun 20, 2016; REACH/SVHC_SOURCE: MATERIAL DECLARATION; REACH/SVHC_STATUS: UNAFFECTED; ROHS: Exempt; Rated Current: N/A; Rated Power: 0.05W; Rated Voltage: 30V; Resistor Type: THICK FILM; Revision: R004; RoHS Status: ROHS_COMPLIANT; Rtd Current: N/A; Rtd Power: 0.063W; Rtd Voltage: 50V; Status: Released; Type: Resistor; Vendor: VISHAY; Vendor Part Number: CRCW020151R0JNED; Vendor Part Status: Active; WEIGHT: 0.00065g
